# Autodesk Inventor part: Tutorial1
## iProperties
Shininess: 64.0
Length Units: 11269
Angle Units: 11279
Time Units: 11290
Mass Units: 11283
Length Display Precision: 3
Angle Display Precision: 2
Compacted: True
Part Number: Tutorial1
Document SubType Name: Modeling
Created: 2002-11
Designer: deepak
Density: 0.0
Volumn: 0.0
Area: 0.0
PropertySet Name: Model Information
Control State: 0
Master: False
Checked Out: False
Author: deepak
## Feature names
1. Extrusion1
